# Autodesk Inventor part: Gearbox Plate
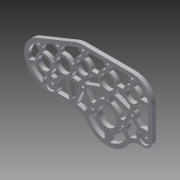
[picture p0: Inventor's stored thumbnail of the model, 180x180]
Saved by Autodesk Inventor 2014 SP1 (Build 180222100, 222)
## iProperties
Created: 2014-11
Part Number: Gearbox Plate
Material: Aluminum 6061
Document SubType Name: Sheet Metal
Designer: Michael
Density: 2.71 g/cm^3
Appearance: Aluminum - Flat
Sheet Metal Rule: Default
Mass: 155.766 g
Surface Area: 356.193 cm^2
Volume: 57.4784 cm^3
Author: Michael
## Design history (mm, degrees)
node "Face1"
  sketch "Sketch1" dims "d12" = 63.5 (= DrivenGear), "d35" = 22.352, "d96" = 4.2545 (derived)
    geometry: L1 (-39.37, 48.336)-(0, 48.336); L2 (0, 0)-(0, 48.336); L3 (0, 0)-(-38.1, 0); L4 (0, 48.336)-(-31.75, 48.336); L5 (-110.258, 47.105)-(-91.237, 0); L6 (-112.73, 53.228)-(-51.353, 78.012); L7 (-39.37, 80.34)-(39.37, 80.34); L8 (-100.747, 23.552)-(-39.37, 48.336); L9 (71.374, 48.336)-(71.374, 0); L10 (58.674, -12.7)-(52.771, -12.7); L11 (-91.237, -12.86)-(-52.655, -12.86); L12 (39.37, 80.34)-(-39.37, 80.34); L13 (-51.353, 78.012)-(-112.73, 53.228); L14 (-91.237, -12.86)-(-52.655, -12.86); L15 (58.674, -12.7)-(55.722, -12.7); L16 (71.374, 0)-(71.374, 48.336); L17 (-52.655, -12.86)-(-91.237, -12.86); L18 (52.771, -12.7)-(58.674, -12.7); L19 (-110.258, 47.105)-(-100.061, 21.852); L20 (-70.059, 35.944)-(-82.042, 65.62); L21 (-39.37, 48.336)-(-39.37, 73.736); L22 (-39.37, 48.336)-(-39.37, 22.936); L23 (0, 48.336)-(39.37, 48.336); L24 (39.37, 48.336)-(39.37, 73.736); L25 (39.37, 22.936)-(39.37, 48.336); L26 (39.37, 48.336)-(71.374, 48.336); L27 (0, 0)-(0, -39.688); L28 (-91.237, 0)-(-65.874, 25.581); L29 (-65.874, 25.581)-(-55.574, -12.86); L30 (-39.37, 22.936)-(-55.574, -12.86); L31 (39.37, 22.936)-(23.812, 0); L32 (-39.37, 22.936)-(-23.812, 0); L33 (-100.747, 23.552)-(-130.423, 11.569); L34 (-108.474, 35.267)-(-103.322, 37.348); L35 (-103.322, 37.348)-(-105.174, 41.934); L36 (-105.174, 41.934)-(-110.326, 39.853); L37 (-110.326, 39.853)-(-108.474, 35.267); L38 (-114.543, 20.978)-(-112.462, 15.826); L39 (-112.462, 15.826)-(-129.383, 8.993); L40 (-129.383, 8.993)-(-131.464, 14.145); L41 (-131.464, 14.145)-(-114.543, 20.978); L42 (-81.113, 6.266)-(-85.059, 10.178); L43 (-85.059, 10.178)-(-70.542, 24.819); L44 (-70.542, 24.819)-(-66.596, 20.907); L45 (-66.596, 20.907)-(-81.113, 6.266); L46 (-67.452, 20.736)-(-62.085, 22.174); L47 (-62.085, 22.174)-(-52.698, -12.86); L48 (-52.698, -12.86)-(-58.065, -14.298); L49 (-58.065, -14.298)-(-67.452, 20.736); L50 (-39.37, 73.99)-(39.37, 73.99); L51 (65.024, 0)-(65.024, 48.336); L52 (58.674, -6.35)-(52.771, -6.35); L53 (-91.237, -6.51)-(-52.655, -6.51); L54 (-115.367, 45.316)-(-48.975, 72.124); L55 (-58.623, -12.86)-(-53.562, -15.151); L56 (-53.562, -15.151)-(-39.601, 15.688); L57 (-39.601, 15.688)-(-44.663, 17.98); L58 (-44.663, 17.98)-(-58.623, -12.86); L59 (-89.033, 31.279)-(-86.952, 26.127); L60 (-86.952, 26.127)-(-83.093, 27.685); L61 (-83.093, 27.685)-(-85.173, 32.837); L62 (-85.173, 32.837)-(-89.033, 31.279); L63 (-78.318, 48.978)-(-73.166, 51.059); L64 (-73.166, 51.059)-(-79.466, 66.66)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; C1 r 25.4 at (0, 0); C2 r 22.86 at (0, 48.336); C3 r 7.62 at (-39.37, 48.336); C4 r 7.62 at (39.37, 48.336); C5 r 10.16 at (0, 48.336); C6 r 13.5 at (0, 0); C7 r 2.489 at (-91.237, 0); C8 r 2.489 at (-110.258, 47.105); C9 r 7.62 at (-100.747, 23.552); C10 r 25.4 at (-70.059, 35.944); C11 r 9.525 at (-91.237, 0); C12 r 9.779 at (-100.747, 23.552); C13 r 9.779 at (-39.37, 48.336); C14 r 9.779 at (39.37, 48.336); C15 r 11.176 at (0, 48.336); C16 r 14.351 at (0, 0); C17 r 9.525 at (58.674, 0); C18 r 2.489 at (-39.37, 22.936); C19 r 2.489 at (-39.37, 73.736); C20 r 2.489 at (39.37, 73.736); C21 r 2.489 at (39.37, 22.936); C22 r 2.489 at (58.674, 0); C23 r 2.489 at (-23.812, 0); C24 r 2.489 at (23.812, 0); C25 r 1.587 at (20.206, -6.735); C26 r 1.587 at (-20.206, -6.735); C27 r 1.587 at (0, 23.244); C28 r 2.489 at (0, 73.99); C29 r 2.489 at (-79.664, 59.732); C30 r 6.35 at (0, 73.99); C31 r 6.35 at (-79.664, 59.732); A1 r 38.1 centre (0, 0) between (-38.1, 0) and (-30.706, -22.555); A2 r 32.004 centre (-39.37, 48.336) between (-51.353, 78.012) and (-39.37, 80.34); A3 r 32.004 centre (39.37, 48.336) between (39.37, 80.34) and (71.374, 48.336); A4 r 32.004 centre (-100.747, 23.552) between (-112.73, 53.228) and (-125.169, 2.868); A5 r 12.7 centre (58.674, 0) between (58.674, -12.7) and (71.374, 0); A6 r 44.467 centre (-91.237, 31.607) between (-125.169, 2.868) and (-91.237, -12.86); A7 r 32.004 centre (-39.37, 48.336) between (-39.37, 80.34) and (-51.353, 78.012); A8 r 32.004 centre (-100.747, 23.552) between (-112.73, 53.228) and (-125.169, 2.868); A9 r 44.467 centre (-91.237, 31.607) between (-125.169, 2.868) and (-91.237, -12.86); A10 r 12.7 centre (58.674, 0) between (58.674, -12.7) and (71.374, 0); A11 r 32.004 centre (39.37, 48.336) between (71.374, 48.336) and (39.37, 80.34); A12 r 39.688 centre (0, 0) between (-32.107, -23.329) and (32.177, -23.232); A13 r 25.4 centre (-52.655, -38.26) between (-32.107, -23.329) and (-52.655, -12.86); A14 r 25.4 centre (52.771, -38.1) between (52.771, -12.7) and (32.177, -23.232); A15 r 25.4 centre (-52.655, -38.26) between (-32.107, -23.329) and (-52.655, -12.86); A16 r 39.687 centre (0, 0) between (-32.107, -23.329) and (32.177, -23.232); A17 r 25.4 centre (52.771, -38.1) between (52.771, -12.7) and (32.177, -23.232); A18 r 11.906 centre (-91.237, 0) between (-81.113, 6.266) and (-85.059, 10.178); A19 r 7.252 centre (-110.258, 47.105) between (-105.174, 41.934) and (-116.651, 43.682); A20 r 14.034 centre (-39.37, 48.336) between (-53.165, 45.762) and (-42.148, 62.092); A21 r 7.252 centre (-39.37, 73.736) between (-36.592, 67.038) and (-46.58, 72.956); A22 r 7.252 centre (39.37, 73.736) between (42.148, 67.038) and (32.123, 73.99); A23 r 14.034 centre (39.37, 48.336) between (25.614, 51.114) and (36.592, 62.092); A24 r 8.045 centre (-23.812, 0) between (-31.194, -3.199) and (-24.856, -7.977); A25 r 8.045 centre (23.812, 0) between (24.888, -7.973) and (31.207, -3.17); A26 r 12.7 centre (58.674, 0) between (53.185, 11.453) and (65.024, 10.999); A27 r 7.252 centre (39.37, 22.936) between (36.592, 29.635) and (42.148, 29.635); A28 r 25.654 centre (39.37, 48.336) between (65.024, 48.336) and (39.37, 73.99); A29 r 6.35 centre (58.674, 0) between (58.674, -6.35) and (65.024, 0); A30 r 31.75 centre (52.771, -38.1) between (52.771, -6.35) and (27.029, -19.515); A31 r 33.338 centre (0, 0) between (-26.97, -19.596) and (27.029, -19.515); A32 r 31.75 centre (-52.655, -38.26) between (-26.97, -19.596) and (-52.655, -6.51); A33 r 38.117 centre (-91.237, 31.607) between (-120.324, 6.972) and (-91.237, -6.51); A34 r 25.654 centre (-100.747, 23.552) between (-109.26, 47.753) and (-120.324, 6.972); A35 r 25.654 centre (-39.37, 48.336) between (-39.37, 73.99) and (-48.975, 72.124); A36 r 6.35 centre (-79.664, 59.732) between (-85.552, 57.355) and (-80.102, 53.397); A37 r 6.35 centre (0, 73.99) between (2.778, 68.28) and (-6.35, 73.99); A38 r 38.117 centre (-90.968, 31.526) between (-123.355, 11.427) and (-102.071, -4.938); A39 r 11.906 centre (-91.237, 0) between (-98.148, 9.695) and (-102.071, -4.938); A40 r 14.034 centre (-100.747, 23.552) between (-112.462, 15.826) and (-98.173, 9.757); A41 r 14.034 centre (-100.747, 23.552) between (-108.474, 35.267) and (-114.543, 20.978); A42 r 7.252 centre (-110.258, 47.105) between (-116.651, 43.682) and (-110.326, 39.853); A43 r 25.654 centre (-100.747, 23.552) between (-116.651, 43.682) and (-125.436, 16.58); A44 r 14.034 centre (-100.747, 23.552) between (-89.033, 31.279) and (-103.322, 37.348); A45 r 7.252 centre (-110.258, 47.105) between (-105.174, 41.934) and (-103.633, 50.054); A46 r 15.431 centre (-70.059, 35.944) between (-78.318, 48.978) and (-85.173, 32.837); A47 r 6.35 centre (-79.664, 59.732) between (-85.552, 57.355) and (-80.102, 53.397); A48 r 14.034 centre (-100.747, 23.552) between (-93.021, 11.837) and (-86.952, 26.127); A49 r 15.431 centre (-70.059, 35.944) between (-83.093, 27.685) and (-74.239, 21.091); A50 r 11.906 centre (-91.237, 0) between (-85.059, 10.178) and (-92.996, 11.776); A51 r 11.906 centre (-91.237, 0) between (-81.268, -6.51) and (-81.113, 6.266); A52 r 15.431 centre (-70.059, 35.944) between (-57.025, 44.203) and (-73.166, 51.059); A53 r 6.35 centre (-79.664, 59.732) between (-74.95, 55.478) and (-73.776, 62.11); A54 r 14.034 centre (-39.37, 48.336) between (-42.148, 62.092) and (-53.165, 45.762); A55 r 7.252 centre (-39.37, 73.736) between (-46.58, 72.956) and (-42.148, 67.038); A56 r 14.034 centre (-39.37, 48.336) between (-51.085, 40.61) and (-42.148, 34.58); A57 r 15.431 centre (-70.059, 35.944) between (-57.726, 26.671) and (-54.944, 39.051); A58 r 7.252 centre (-39.37, 22.936) between (-42.148, 29.635) and (-45.915, 26.058); A59 r 31.75 centre (-52.655, -38.26) between (-36.862, -10.717) and (-49.712, -6.647); A60 r 7.252 centre (-39.37, 22.936) between (-39.601, 15.688) and (-39.184, 15.687); A61 r 8.045 centre (-23.812, 0) between (-30.35, 4.689) and (-31.194, -3.199); A62 r 7.252 centre (-39.37, 22.936) between (-46.203, 20.509) and (-44.663, 17.98); A63 r 14.034 centre (-39.37, 48.336) between (-25.614, 51.114) and (-36.592, 62.092); A64 r 15.431 centre (0, 48.336) between (-2.778, 63.515) and (-15.178, 51.114)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; 17 further points; 1 other entity
    constraints: 434 end point, 251 point on circle, 132 centre point, 73 parallel, 56 tangent, 53 perpendicular, 51 point on line, 47 coincident, 44 concentric, 42 collinear, 9 midpoint, 7 vertical alignment, 4 horizontal alignment, 4 symmetric about line, 3 equal length, 3 equal radius, 3 vertical, 2 horizontal, 99 other
    dimensions: "d1" = 50.8 diameter of C1 (= HSpeed2); "d2" = 45.72 diameter of C2 (= HSpeed1); "d5" = 15.24 diameter of C3 (= CIMgear); "d7" = 15.24 diameter of C4 (= CIMgear); "d10" = 20.32 diameter of C5 (= LSpeed1); "d11" = 76.2 diameter of A1 (= LSpeed2); "d13" = 27.0002 diameter of C6 (derived); "d16" = 0 distance between parallel lines of L1 L4; "d17" = 64.008 diameter of A2 (= CIM); "d18" = 64.008 diameter of A3 (= CIM); "d19" = 64.008 diameter of A4 (= CIM); "d20" = 4.9784 diameter of C7; "d21" = 4.9784 diameter of C8 (derived); "d22" = 25.4 distance of L5.start L8.start; "d23" = 15.24 diameter of C9 (= CIMgear); "d24" = 50.8 diameter of C10 (= InterGear); "d29" = 12.7 radius of A5; "d30" = 19.05 diameter of C11; "d34" = 19.558 diameter of C12 (derived); "d36" = 19.558 diameter of C13; "d37" = 19.558 diameter of C14 (derived); "d38" = 22.352 diameter of C15; "d39" = 28.702 diameter of C16; "d40" = 19.05 diameter of C17; "d41" = 4.9784 diameter of C18 (derived); "d42" = 4.9784 diameter of C19 (derived); "d43" = 4.9784 diameter of C20 (derived); "d44" = 4.9784 diameter of C21 (derived); "d49" = 4.9784 diameter of C22 (derived); "d59" = 79.375 diameter of A12 (derived); "d60" = 25.4 radius of A13; "d61" = 25.4 radius of A14; "d89" = 4.2545 dimension on C12; "d90" = 2.38125 radial gap between concentric circles of C11 A18; "d91" = 4.7625 radial gap between concentric circles of A19 C8; "d92" = 4.9784 diameter of C23; "d93" = 4.9784 diameter of C24 (derived); "d94" = 23.8125 distance of L27.start C23.centre; "d95" = 23.8125 distance of C24.centre point (0, 0) (derived); "d99" = 4.7625 dimension on C18 (derived); "d100" = 4.2545 radial gap between concentric circles of C13 A20 (derived); "d101" = 4.2545 dimension on C15 (derived); "d102" = 4.2545 radial gap between concentric circles of C14 A23 (derived); "d103" = 4.7625 radial gap between concentric circles of C19 A21 (derived); "d104" = 4.7625 radial gap between concentric circles of C20 A22 (derived); "d105" = 4.7625 radial gap between concentric circles of C21 A27 (derived); "d106" = 5.55625 radial gap between concentric circles of C24 A25 (derived); "d107" = 5.55625 radial gap between concentric circles of A24 C23 (derived); "d108" = 7.9375 dimension on C16; "d109" = 3.175 radial gap between concentric circles of A26 C17; "d110" = 5.55625 distance between parallel lines of L35 L37; "d111" = 5.55625 distance between parallel lines of L39 L41 (derived); "d112" = 5.55625 distance between parallel lines of L43 L45 (derived); "d113" = 5.55625 distance between parallel lines of L47 L49 (derived); "d114" = 6.35 distance between parallel lines of L6 L54; "d115" = 5.55625 distance between parallel lines of L58 L56 (derived); "d116" = 5.55625 distance between parallel lines of L62 L60 (derived); "d117" = 5.55625 distance between parallel lines of L64 L66 (derived); "d118" = 5.55625 distance between parallel lines of L70 L68 (derived); "d119" = 5.55625 distance between parallel lines of L74 L72 (derived); "d120" = 5.55625 distance between parallel lines of L76 L78 (derived); "d122" = 20.20558 horizontal distance of C25.centre point (0, 0); "d123" = 6.73519 vertical distance of point (0, 0) C25.centre; "d124" = 3.175 diameter of C25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
feature "Corner Round1" dims "d160" = 1.5875
hole "Hole1" diameter "d163" = 19.05; stored, may be unused: countersink angle "d167" = 82 deg, drill point angle "d169" = 0 deg; dims "d161" = 25.4, "d162" = 25.4, "d164" = 19.05, "d165" = 9.525, "d166" = 6.35, "d168" = 3.175
hole "Hole2" diameter "d172" = 19.05; stored, may be unused: countersink angle "d176" = 82 deg, drill point angle "d178" = 0 deg; dims "d170" = 25.4, "d171" = 25.4, "d173" = 19.05, "d174" = 9.525, "d175" = 6.35, "d177" = 3.175
body "Solid1"
face "Plate1" dims "Thickness" = 6.35 (derived)
other parameters: "CIMgear" = 15.24 [user parameter; used in 3 equation terms], "DrivenGear" = 63.5 [user parameter; used in 1 equation term], "HSpeed1" = 45.72 [user parameter; used in 1 equation term], "HSpeed2" = 50.8 [user parameter; used in 1 equation term], "LSpeed1" = 20.32 [user parameter; used in 1 equation term], "LSpeed2" = 76.2 [user parameter; used in 1 equation term], "CIM" = 64.008 [user parameter; used in 3 equation terms], "InterGear" = 50.8 [user parameter; used in 1 equation term], "KFactor" = 4.4, "BendRadius" = 6.35 (derived), "BendReliefWidth" = 6.35 (derived), "BendReliefDepth" = 3.175 (derived), "CornerReliefSize" = 25.4 (derived), "SeamGap" = 0.00508, "MinimumRemnant" = 12.7 (derived), "TransitionRadius" = 6.35 (derived), "JacobiRadiusSize" = 6.35 (derived), "GapSize" = 6.35 (derived), "d50" = 6.35 (derived), "Stage2Distance" = 48.3362 [user parameter], "StageInterDistance" = 33.0962 [user parameter], "Dog" = 27.0002 [user parameter]
